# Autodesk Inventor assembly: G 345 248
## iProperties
Company: Mayer & Müller AG Schaltgeräte
Created: 2006-03
Part Number: G 345 248
Material: Geschweißt
Document SubType Name: Weldment
Designer: I.Baliuc
Description: Druckplatte
Mass: 1395.23 g
Surface Area: 427.716 cm^2
Volume: 177.848 cm^3
Density: 7.84506 g/cm^3
Author: T.Messerschmitt
Revision Number: 345248
